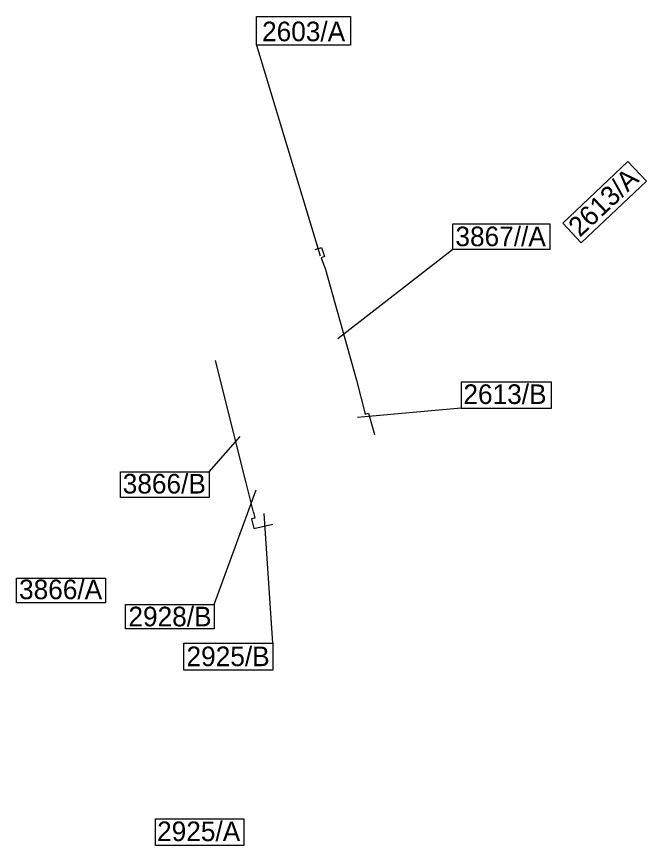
# Model space of a CAD drawing. Extents: x -526772.8 to -526724.6, y -1078509.1 to -1078445.7.
import ezdxf

# ---------------------------------------------------------------- set-up
doc = ezdxf.new("R2010")
doc.units = 0
doc.layers.add('Vrstva 43', color=7, linetype='Continuous')
doc.layers.add('Vrstva 47', color=7, linetype='Continuous')

msp = doc.modelspace()

# ---------------------------------------------------------------- linework, layer by layer
at = {"layer": 'Vrstva 43'}
for p, q in [((-526755.278, -1078481.241), (-526757.602, -1078471.987)), ((-526754.698, -1078483.611), (-526755.278, -1078481.241))]:
    msp.add_line(p, q, dxfattribs=at)
for points in [[(-526749.969, -1078463.508), (-526749.479, -1078463.348), (-526749.266, -1078464.05), (-526749.513, -1078464.135), (-526749.188, -1078465.03)], [(-526749.188, -1078465.03), (-526746.815, -1078473.504), (-526746.139, -1078476.093), (-526745.897, -1078476.037), (-526745.429, -1078477.67)], [(-526754.698, -1078483.611), (-526754.585, -1078484.047), (-526754.838, -1078484.115), (-526754.672, -1078484.845), (-526753.219, -1078484.524)]]:
    msp.add_lwpolyline(points, dxfattribs=at)
at = {"layer": 'Vrstva 47'}
for p, q in [((-526754.448, -1078447.87), (-526749.583, -1078463.981)), ((-526739.441, -1078463.509), (-526748.245, -1078470.333)), ((-526738.802, -1078475.649), (-526746.742, -1078476.367)), ((-526758.087, -1078480.506), (-526755.708, -1078477.821)), ((-526757.705, -1078490.652), (-526754.492, -1078481.895)), ((-526753.213, -1078493.617), (-526753.862, -1078483.701))]:
    msp.add_line(p, q, dxfattribs=at)
for points in [[(-526754.448, -1078445.684), (-526747.272, -1078445.684), (-526747.272, -1078447.87), (-526754.448, -1078447.87)], [(-526731.04, -1078461.488), (-526726.055, -1078456.771), (-526724.639, -1078458.268), (-526729.624, -1078462.985)], [(-526739.441, -1078461.543), (-526732.016, -1078461.543), (-526732.016, -1078463.509), (-526739.441, -1078463.509)], [(-526738.802, -1078475.649), (-526731.907, -1078475.649), (-526731.907, -1078473.651), (-526738.802, -1078473.651)], [(-526764.858, -1078480.506), (-526758.087, -1078480.506), (-526758.087, -1078482.473), (-526764.858, -1078482.473)], [(-526772.805, -1078488.654), (-526766.004, -1078488.654), (-526766.004, -1078490.527), (-526772.805, -1078490.527)], [(-526764.475, -1078490.652), (-526757.705, -1078490.652), (-526757.705, -1078492.525), (-526764.475, -1078492.525)], [(-526760.014, -1078493.617), (-526753.213, -1078493.617), (-526753.213, -1078495.678), (-526760.014, -1078495.678)], [(-526762.174, -1078507.066), (-526755.435, -1078507.066), (-526755.435, -1078509.095), (-526762.174, -1078509.095)]]:
    msp.add_lwpolyline(points, close=True, dxfattribs=at)

# ---------------------------------------------------------------- texts
for s, p in [('2603/A', (-526754.032, -1078447.572)), ('3867//A', (-526739.246, -1078463.251)), ('2613/B', (-526738.634, -1078475.322)), ('3866/B', (-526764.689, -1078482.172)), ('3866/A', (-526772.618, -1078490.257)), ('2928/B', (-526764.252, -1078492.333)), ('2925/B', (-526759.809, -1078495.382)), ('2925/A', (-526762.06, -1078508.766))]:
    msp.add_text(s, height=1.5, dxfattribs=at).set_placement(p)
msp.add_text('2613/A', height=1.5, rotation=43.41511, dxfattribs=at).set_placement((-526729.73, -1078462.613))

doc.saveas('drawing.dxf')
